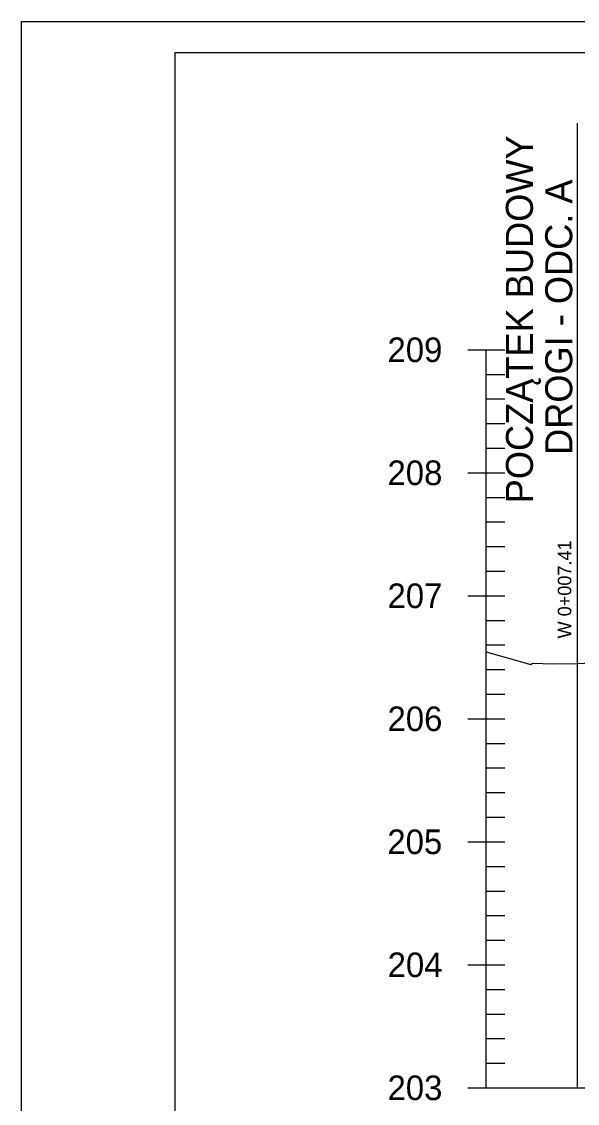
# Model space of a CAD drawing. Extents: x 6513080 to 6513380, y 6022307 to 6022469.
# Drawn here: x 6513079.9 to 6513125.1, y 6022367.3 to 6022455.2 of the extents above; entities that cross this region are included whole.
import ezdxf

# ---------------------------------------------------------------- set-up
doc = ezdxf.new("R2010")
doc.units = 0
for name, color, linetype in [('1', 7, 'Continuous'), ('42', 7, 'Continuous'), ('maxp_opisy', 7, 'Continuous'), ('maxp_ramka_2', 7, 'Continuous')]:
    doc.layers.add(name, color=color, linetype=linetype)

msp = doc.modelspace()

# ---------------------------------------------------------------- linework, layer by layer
at = {"layer": '1'}
for p, q in [((6513116.2, 6022428.562), (6513119.2, 6022428.562)), ((6513116.2, 6022428.562), (6513119.2, 6022428.562)), ((6513117.7, 6022368.562), (6513117.7, 6022428.562)), ((6513117.7, 6022426.562), (6513119.2, 6022426.562)), ((6513117.7, 6022424.562), (6513119.2, 6022424.562)), ((6513117.7, 6022422.562), (6513119.2, 6022422.562)), ((6513117.7, 6022420.562), (6513119.2, 6022420.562)), ((6513116.2, 6022418.562), (6513119.2, 6022418.562)), ((6513117.7, 6022416.562), (6513119.2, 6022416.562)), ((6513117.7, 6022414.562), (6513119.2, 6022414.562)), ((6513117.7, 6022412.562), (6513119.2, 6022412.562)), ((6513117.7, 6022410.562), (6513119.2, 6022410.562)), ((6513116.2, 6022408.562), (6513119.2, 6022408.562)), ((6513117.7, 6022406.562), (6513119.2, 6022406.562)), ((6513117.7, 6022404.562), (6513119.2, 6022404.562)), ((6513117.7, 6022402.562), (6513119.2, 6022402.562)), ((6513117.7, 6022400.562), (6513119.2, 6022400.562)), ((6513116.2, 6022398.562), (6513119.2, 6022398.562)), ((6513117.7, 6022396.562), (6513119.2, 6022396.562)), ((6513117.7, 6022394.562), (6513119.2, 6022394.562)), ((6513117.7, 6022392.562), (6513119.2, 6022392.562)), ((6513117.7, 6022390.562), (6513119.2, 6022390.562)), ((6513116.2, 6022388.562), (6513119.2, 6022388.562)), ((6513117.7, 6022386.562), (6513119.2, 6022386.562)), ((6513117.7, 6022384.562), (6513119.2, 6022384.562)), ((6513117.7, 6022382.562), (6513119.2, 6022382.562)), ((6513117.7, 6022380.562), (6513119.2, 6022380.562)), ((6513116.2, 6022378.562), (6513119.2, 6022378.562)), ((6513117.7, 6022376.562), (6513119.2, 6022376.562)), ((6513117.7, 6022374.562), (6513119.2, 6022374.562)), ((6513117.7, 6022372.562), (6513119.2, 6022372.562)), ((6513117.7, 6022370.562), (6513119.2, 6022370.562)), ((6513117.7, 6022368.562), (6513117.7, 6022370.562)), ((6513116.2, 6022368.562), (6513119.2, 6022368.562)), ((6513117.7, 6022368.562), (6513327.7, 6022368.562))]:
    msp.add_line(p, q, dxfattribs=at)
msp.add_lwpolyline([(6513117.7, 6022403.995), (6513121.317, 6022402.987), (6513121.46, 6022403.073), (6513123.129, 6022403.04), (6513125.078, 6022403.068), (6513129.343, 6022403.244)], dxfattribs=at)
at = {"layer": '42'}
for p, q in [((6513125.109, 6022368.568), (6513125.109, 6022446.984)), ((6513125.109, 6022403.061), (6513125.109, 6022415.161))]:
    msp.add_line(p, q, dxfattribs=at)
at = {"layer": 'maxp_ramka_2'}
for points in [[(6513079.898, 6022455.239), (6513379.898, 6022455.239), (6513379.898, 6022306.739), (6513079.898, 6022306.739)], [(6513092.398, 6022309.239), (6513092.398, 6022452.739), (6513377.398, 6022452.739), (6513377.398, 6022309.239)]]:
    msp.add_lwpolyline(points, close=True, dxfattribs=at)

# ---------------------------------------------------------------- texts
at = {"layer": '1'}
for s, p in [('209', (6513109.664, 6022427.562)), ('209', (6513109.664, 6022427.562)), ('208', (6513109.664, 6022417.562)), ('207', (6513109.667, 6022407.562)), ('206', (6513109.667, 6022397.562)), ('205', (6513109.652, 6022387.562)), ('204', (6513109.676, 6022377.562)), ('203', (6513109.667, 6022367.562))]:
    msp.add_text(s, height=2, dxfattribs=at).set_placement(p)
at = {"layer": '42'}
msp.add_text('W 0+007.41', height=1.1, rotation=90, dxfattribs=at).set_placement((6513124.614, 6022405.095))
at = {"layer": 'maxp_opisy'}
for s, p in [('POCZĄTEK BUDOWY', (6513121.499, 6022416.081)), ('DROGI - ODC. A', (6513124.698, 6022420.013))]:
    msp.add_text(s, height=2.2, rotation=90.01624, dxfattribs=at).set_placement(p)

doc.saveas('drawing.dxf')
